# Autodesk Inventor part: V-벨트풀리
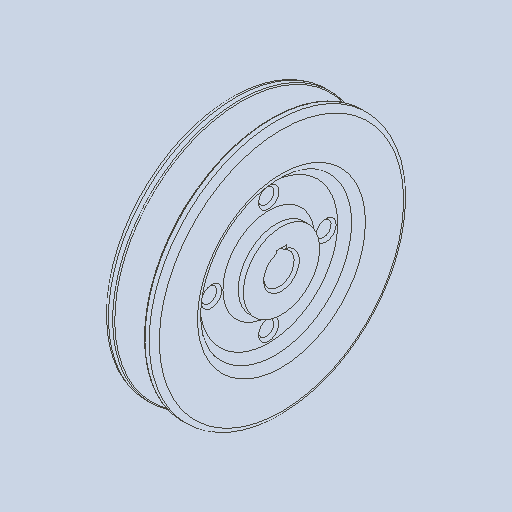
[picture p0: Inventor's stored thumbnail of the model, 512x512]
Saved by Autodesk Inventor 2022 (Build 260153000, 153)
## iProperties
Created: 2015-09
Part Number: V-벨트풀리
Material: 강철, 연강
Document SubType Name: Modeling
Designer: mduedu
Density: 1 g/cm^3
Appearance: 강철
Author: mduedu
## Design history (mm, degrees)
sketch "스케치1"
  geometry: L1 (-10, 0)-(10, 0); L2 (-10, 0)-(-10, 50); L3 (-10, 50)-(-5.976, 50); L4 (-5.976, 50)-(-2.154, 37.5); L5 (-2.154, 37.5)-(2.154, 37.5); L6 (2.154, 37.5)-(5.976, 50); L7 (5.976, 50)-(10, 50); L8 (10, 50)-(10, 0); L9 (0, 0)-(0, 37.5); L10 (-10, 45.5)-(10, 45.5); 3 further points
  constraints: 20 end point, 6 point on line, 3 perpendicular, 2 midpoint, 2 parallel, 2 symmetric about line, 1 coincident, 1 collinear, 1 equal length, 1 horizontal, 1 vertical, 1 vertical alignment
  dimensions: "d0" = 20 distance between parallel lines of L8 L2; "d2" = 100 diameter of L3 L1; "d5" = 8 distance between parallel lines of L5 L10; "d6" = 9.2 distance of point (4.6, 45.5) point (-4.6, 45.5); "d7" = 34 deg angle of L6 L4; "d40" = 4.5 distance between parallel lines of L10 L3
revolve "회전1" sketch "스케치1" stored, may be unused: angle "d8" = 90 deg
sketch "스케치2"
  geometry: C1 r 15 at (0, 0); C2 r 30 at (0, 0); 1 further point
  constraints: 2 centre point, 2 coincident
  dimensions: "d9" = 30 diameter of C1; "d41" = 60 diameter of C2
extrude "돌출5" cut sketch "스케치2" distance "d42" = 5; taper "d43" = 0 deg
hole "구멍2" diameter "d46" = 12; stored, may be unused: countersink angle "d50" = 90 deg, drill point angle "d52" = 118 deg; dims "d44" = 10, "d45" = 10, "d47" = 6, "d48" = 4, "d49" = 2, "d51" = 8
sketch "스케치8"
  geometry: L1 (-2, 5.657)-(2, 5.657); L2 (2, 5.657)-(2, 7.8); L3 (2, 7.8)-(-2, 7.8); L4 (-2, 7.8)-(-2, 5.657); A1 r 6 centre (0, 0) between (-2, 5.657) and (2, 5.657) reference; 1 further point
  constraints: 8 end point, 2 parallel, 2 point on circle, 1 horizontal, 1 perpendicular
  dimensions: "d53" = 4 distance of L2.end L3.end; "d55" = 13.8 dimension on A1 L3
extrude "돌출6" cut sketch "스케치8" extent not by distance; stored distance "d56" = 5; taper "d57" = 0 deg
sketch "스케치9"
  geometry: C1 r 3 at (0, 22.5); 1 further point
  constraints: 1 centre point, 1 vertical alignment
  dimensions: "d61" = 6 diameter of C1; "d62" = 22.5 distance of C1.centre point (0, 0)
extrude "돌출7" cut sketch "스케치9" extent not by distance; stored distance "d63" = 5; taper "d64" = 0 deg
chamfer "모따기3" distance "d65" = 1; stored, may be unused: second distance "d66" = 2, angle "d67" = 45 deg
fillet "모깎기5" dims "d71" = 2, "d72" = 1, "d73" = 0.5
fillet "모깎기6" dims "d74" = 3
fillet "모깎기7" dims "d75" = 3
fillet "모깎기8" dims "d76" = 3
chamfer "모따기4" distance "d82" = 1; stored, may be unused: second distance "d83" = 2, angle "d84" = 45 deg
node "솔리드1"
mirror "대칭2"
pattern_circular "원형 패턴1" dims "d69" = 360 deg
